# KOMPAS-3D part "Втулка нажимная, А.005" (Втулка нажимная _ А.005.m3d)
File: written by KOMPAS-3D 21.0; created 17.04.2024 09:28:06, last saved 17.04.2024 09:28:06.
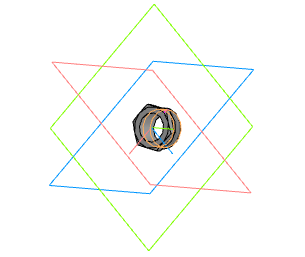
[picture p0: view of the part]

Document properties: Автор: Admin; Полное имя файла: C:\Users\wsr\Desktop\Чертежи\Детали\Втулка нажимная _ А.005.m3d

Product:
- Part/product: Втулка нажимная  | designation А.005
    Масса: 0.002734
  - Body: Тело 1
      Масса: 0.005855

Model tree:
1. Эскиз:1
2. Элемент выдавливания:1
     Расстояние 1 = 2
3. Эскиз:2  (with: Элемент выдавливания:1)
4. Элемент выдавливания:2
     Расстояние 1 = 1.5
5. Эскиз:3  (with: Элемент выдавливания:2)
6. Элемент выдавливания:3
     Расстояние 1 = 3.5
7. Условное изображение резьбы:1  (with: Элемент выдавливания:3)  (labels: M12x1)
     Длина резьбы = 3.5; Шаг резьбы = 1; Номинальный диаметр резьбы = 12
8. Подгонка:1  (with: Элемент выдавливания:3)
9. Фаска:1  (with: Элемент выдавливания:3)
     Угол = 45; Длина 1 = 1; Длина 2 = 1
10. Эскиз:4  (with: Элемент выдавливания:1)
11. Элемент вращения:1  (with: Элемент выдавливания:3)
     Угол 1 = 360
12. Эскиз:5  (with: Элемент выдавливания:1, Элемент вращения:1)
13. Элемент выдавливания:4
     Расстояние 2 = 50

Expressions: 12/2; cil1_24705-2004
